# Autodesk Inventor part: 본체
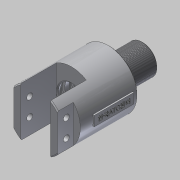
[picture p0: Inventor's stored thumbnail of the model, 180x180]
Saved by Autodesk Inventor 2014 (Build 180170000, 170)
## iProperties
Created: 2019-02
Part Number: 본체
Material: 알루미늄 6061
Document SubType Name: Modeling
Designer: 603-14
Density: 2.71 g/cm^3
Appearance: 알루미늄 - 평지
Mass: 336.883 g
Surface Area: 292.132 cm^2
Volume: 124.311 cm^3
Author: 603-14
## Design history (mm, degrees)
sketch "스케치1"
  geometry: L1 (-36, 0)-(36, 0); L2 (-36, 14)-(-36, 29); L3 (-36, 29)-(2, 29); L4 (2, 29)-(2, 13); L5 (2, 13)-(7, 13); L6 (7, 13)-(7, 15); L7 (7, 15)-(36, 15); L8 (36, 15)-(36, 7); L9 (-36, 14)-(-33.35, 14); L10 (-33.35, 14)-(-33.35, 16.2); L11 (-32.55, 17)-(-29.45, 17); L12 (-28.65, 16.2)-(-28.65, 14); L13 (-28.65, 14)-(-24.35, 14); L14 (-24.35, 14)-(-24.35, 16.2); L15 (-23.55, 17)-(-20.45, 17); L16 (-19.65, 16.2)-(-19.65, 14); L17 (-19.65, 14)-(-16, 14); L18 (-16, 14)-(-16, 16); L19 (-16, 16)-(-9, 16); L20 (-9, 16)-(-9, 4); L21 (-9, 4)-(13, 4); L22 (14, 7)-(36, 7); L23 (-31, 17)-(-31, 19.47); L24 (-22, 17)-(-22, 19.47); L25 (13, 4)-(14, 7); A1 r 0.8 centre (-32.55, 16.2) between (-32.55, 17) and (-33.35, 16.2); A2 r 0.8 centre (-29.45, 16.2) between (-28.65, 16.2) and (-29.45, 17); A3 r 0.8 centre (-23.55, 16.2) between (-23.55, 17) and (-24.35, 16.2); A4 r 0.8 centre (-20.45, 16.2) between (-19.65, 16.2) and (-20.45, 17); 6 further points
  constraints: 50 end point, 13 parallel, 9 perpendicular, 8 point on circle, 8 point on line, 8 tangent, 4 centre point, 3 equal radius, 3 midpoint, 1 coincident, 1 collinear, 1 horizontal
  dimensions: "d1" = 72 distance of L1.start L1.end; "d2" = 5 distance of L4.end L5.end; "d3" = 29 distance of L6.end L7.end; "d4" = 38 distance of L2.end L3.end (derived); "d5" = 58 diameter of L3 L1; "d6" = 30 diameter of L7 L1; "d7" = 26 diameter of L5 L1; "d8" = 27 distance from line of L19.end L2; "d10" = 4.7 distance of point (-33.35, 17) point (-28.65, 17); "d11" = 4.7 distance of point (-24.35, 17) point (-19.65, 17); "d12" = 7 distance of L18.end L19.end; "d15" = 28 diameter of L9 L1; "d16" = 34 diameter of L11 L1; "d17" = 34 diameter of L15 L1; "d18" = 32 diameter of L19 L1; "d19" = 28 diameter of L13 L1 (= d15); "d20" = 28 diameter of L17 L1 (= d15); "d21" = 8 diameter of L21 L1; "d23" = 14 diameter of L22 L1; "d24" = 0.8 radius of A1; "d25" = 5 distance between parallel lines of L23 L2; "d26" = 9 distance between parallel lines of L24 L23; "d27" = 22 distance of L8.end L22.start; "d28" = 1 horizontal distance of L22.start L21.end
revolve "회전1" sketch "스케치1" stored, may be unused: angle "d29" = 90 deg
feature "스레드1" dims "d30" = 10, "d31" = 0
chamfer "모따기1" distance "d32" = 1; stored, may be unused: second distance "d33" = 2, angle "d34" = 45 deg
chamfer "모따기2" distance "d35" = 1; stored, may be unused: second distance "d36" = 2, angle "d37" = 45 deg
sketch "스케치2"
  geometry: C1 r 29 at (0, 0) reference; C2 r 15 at (0, 0) reference; 2 further points
  constraints: 1 coincident
extrude "돌출1" join sketch "스케치2" distance "d38" = 36; taper "d39" = 0 deg
sketch "스케치3"
  geometry: L1 (-15, -34.301)-(15, -34.301); L2 (15, -34.301)-(15, 34.301); L3 (15, 34.301)-(-15, 34.301); L4 (-15, 34.301)-(-15, -34.301); L5 (-15, -34.301)-(15, 34.301); L6 (15, -34.301)-(-15, 34.301); 1 further point
  constraints: 12 end point, 2 midpoint, 2 parallel, 1 horizontal, 1 perpendicular
extrude "돌출2" cut sketch "스케치3" distance "d40" = 36; taper "d41" = 0 deg
sketch "스케치4"
  geometry: L1 (22, -18.894)-(22, 18.894); L2 (-22, 18.894)-(-22, -18.894); L3 (-22, -36.828)-(22, 36.828); L4 (22, -36.828)-(-22, 36.828); L5 (15, 24.819)-(15, -24.819) reference; L6 (-15, -24.819)-(-15, 24.819) reference; A1 r 29 centre (0, 0) between (15, -24.819) and (15, 24.819) reference; A2 r 29 centre (0, 0) between (-15, 24.819) and (-15, -24.819) reference; 1 further point
  constraints: 8 end point, 4 point on circle, 2 midpoint, 1 parallel
  dimensions: "d42" = 44 distance between parallel lines of L1 L2
extrude "돌출3" cut sketch "스케치4" distance "d43" = 16; taper "d44" = 0 deg
sketch "스케치5"
  geometry: L1 (0, 0)-(0, 37.789) reference; L2 (16, 0)-(0, 0) reference; L3 (16, 0)-(16, 37.789) reference; L4 (0, 37.789)-(16, 37.789) reference; L5 (0, 0)-(0, 37.789) reference; C1 r 3 at (9, 27.894); C2 r 3 at (9, 9.894); 1 further point
  constraints: 2 centre point, 1 vertical alignment
  dimensions: "d45" = 9 distance from line of C1.centre L1; "d46" = 18 distance of C2.centre C1.centre; "d47" = 6 diameter of C1; "d48" = 6 diameter of C2; "d66" = 9 vertical distance of point (72, 18.894) C1.centre
extrude "돌출4" cut sketch "스케치5" distance "d49" = 56; taper "d50" = 0 deg
chamfer "모따기3" distance "d51" = 1; stored, may be unused: second distance "d52" = 2, angle "d53" = 45 deg
feature "스레드2" dims "d54" = 18, "d55" = 0
node "작업 평면1"
sketch "스케치6"
  geometry: L1 (2, 28)-(2, -28) reference; L2 (-43, -5)-(-3, -5); L3 (-3, -5)-(-3, 5); L4 (-3, 5)-(-43, 5); L5 (-43, 5)-(-43, -5); L6 (-43, -5)-(-3, 5); L7 (-3, -5)-(-43, 5); L8 (0, 0)-(-56.112, 0); L9 (1, -29)-(1, 29) reference; 2 further points
  constraints: 14 end point, 3 midpoint, 2 parallel, 2 perpendicular, 1 horizontal, 1 horizontal alignment
  dimensions: "d57" = 5 distance between parallel lines of L1 L3; "d58" = 40 distance of L3.end L4.end; "d59" = 10 distance of L4.end L2.start
extrude "돌출5" join sketch "스케치6" stored distance "d60" = 56; taper "d61" = 0 deg
sketch "스케치7"
  geometry: L1 (-43, -5)-(-3, -5) reference; L2 (-3, -5)-(-3, 5) reference; L3 (-3, 5)-(-43, 5) reference; L4 (-43, 5)-(-43, -5) reference; 2 further points
  constraints: 1 other
  dimensions: "d62" = 20 distance from line of L4 point (-23, 0); "d63" = 5 distance from line of L1 point (-23, 0)
feature "엠보싱1" sketch "스케치7" dims "d64" = 0.5, "d65" = 0
node "솔리드1"
node "투영된 루프1"
node "투영된 루프2"
node "투영된 루프3"
node "투영된 루프4"
node "투영된 루프5"
